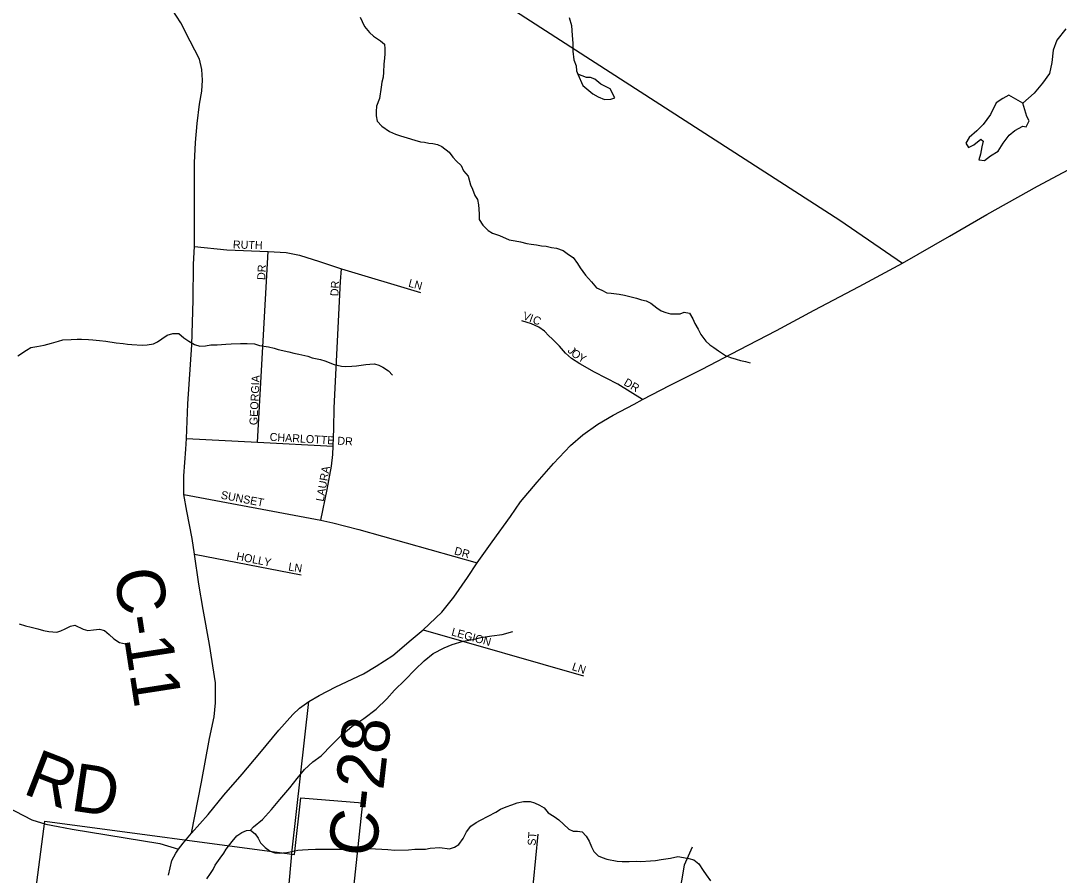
# Model space of a CAD drawing. Extents: x 1310247 to 1664935, y 235267 to 584339.
# Drawn here: x 1518278 to 1524766, y 357083 to 362419 of the extents above; entities that cross this region are included whole.
import ezdxf

# ---------------------------------------------------------------- set-up
doc = ezdxf.new("R2010")
doc.units = 0
for name, color, linetype in [('GM_X_City_Street', 7, 'Continuous'), ('GM_X_Corporation', 7, 'Continuous'), ('GM_X_County_Road', 7, 'Continuous'), ('GM_X_County_Road_Text', 7, 'Continuous'), ('GM_X_Minor_Lake', 7, 'Continuous'), ('GM_X_Minor_River', 7, 'Continuous'), ('GM_X_State_Route', 7, 'Continuous'), ('GM_X_Township_Road', 7, 'Continuous'), ('GM_X_Township_Road_Text', 7, 'Continuous'), ('GM_X_Township_Subdivision', 7, 'Continuous'), ('GM_X_Township_Subdivision_Text', 7, 'Continuous')]:
    doc.layers.add(name, color=color, linetype=linetype)

msp = doc.modelspace()

# ---------------------------------------------------------------- linework, layer by layer
at = {"layer": 'GM_X_City_Street'}
msp.add_lwpolyline([(1519849.1, 356020.4), (1519880.1, 356293.4), (1519914.3, 356582.7), (1519973.8, 357238.6)], dxfattribs=at)
at = {"layer": 'GM_X_Corporation'}
msp.add_lwpolyline([(1518354.2, 356845.4), (1518428.4, 357420.8), (1519987.1, 357211.2), (1520027.7, 357566.1), (1520412.5, 357535.3), (1520260.1, 356104.2)], dxfattribs=at)
at = {"layer": 'GM_X_County_Road'}
for points in [[(1519345.4, 357344.8), (1519406.5, 357663), (1519457, 357935.5), (1519485.5, 358071.7), (1519495.6, 358159.2), (1519493.9, 358283.6), (1519457, 358524.1), (1519418.3, 358742.7), (1519391.4, 358900.8), (1519364.4, 359087.5), (1519349.3, 359185), (1519315.1, 359356.1), (1519297.6, 359460.2), (1519297.1, 359577.2), (1519308.4, 359744.2), (1519313, 359810.1), (1519321.2, 360027.4), (1519346, 360395.8), (1519354.2, 360674.5), (1519357, 360899), (1519362.5, 361009.1), (1519364.3, 361531.5), (1519368.9, 361658.9), (1519380.8, 361777.1), (1519394.6, 361899), (1519408.3, 361979.7), (1519412.9, 362047.5), (1519409.2, 362114.4), (1519394.6, 362178.6), (1519336.8, 362292.3), (1519278.1, 362405.9), (1519196.6, 362530.6)], [(1519973.8, 357238.6), (1520077.9, 358167.8)]]:
    msp.add_lwpolyline(points, dxfattribs=at)
at = {"layer": 'GM_X_Minor_Lake'}
for points in [[(1524538.4, 361905.7), (1524451, 361955.4), (1524412.5, 361933.9), (1524371.9, 361906.5), (1524336.6, 361834.8), (1524289.4, 361771.3)], [(1524289.4, 361771.3), (1524250.7, 361731.8), (1524203.8, 361690.4), (1524181.2, 361654.7), (1524198.8, 361628.3), (1524231.1, 361643.8), (1524275.9, 361679.2), (1524289.7, 361666.9), (1524281.1, 361632.9), (1524274.3, 361586.8), (1524263.7, 361550.9), (1524299.7, 361546.2), (1524336.3, 361575.8), (1524385, 361605.1), (1524415.9, 361654.7), (1524452.8, 361704.3), (1524487.4, 361733.9), (1524538, 361761.1), (1524558, 361756.8), (1524576.7, 361794.6), (1524563.1, 361821), (1524538.4, 361905.7)]]:
    msp.add_lwpolyline(points, dxfattribs=at)
at = {"layer": 'GM_X_Minor_River'}
for points in [[(1520398.8, 362443), (1520410.2, 362414.6), (1520425.6, 362384.2), (1520456.8, 362345.5), (1520482.3, 362322.9), (1520525.7, 362293.9), (1520551.3, 362273.3), (1520552.7, 362243.2), (1520552.1, 362213.1), (1520549.5, 362185.1), (1520546.7, 362149), (1520543.7, 362099), (1520541, 362066.9), (1520534.3, 362037), (1520529.7, 362005), (1520518.1, 361933), (1520501.1, 361885.2), (1520498.4, 361853.2), (1520497.8, 361825.1), (1520505.2, 361792.9), (1520534.5, 361760.2), (1520581.8, 361727.1), (1520619.5, 361712.2), (1520651.3, 361701.6), (1520691.1, 361688.7), (1520740.8, 361673.6), (1520774.6, 361662.9), (1520800.6, 361660.3), (1520826.5, 361655.8), (1520852.4, 361653.2), (1520882.3, 361646.6), (1520908.1, 361634), (1520953.4, 361599), (1520976.7, 361568.4), (1521000.2, 361541.8), (1521029.6, 361515.1), (1521043, 361482.8), (1521072.3, 361448.1), (1521087.2, 361395.6), (1521100.6, 361367.2), (1521113.8, 361328.9), (1521131.2, 361302.4), (1521138.5, 361270.2), (1521141.4, 361214), (1521142.6, 361177.8), (1521163.9, 361143.3), (1521197.2, 361110.5), (1521224.8, 361091.9), (1521268.6, 361078.9), (1521330.1, 361051.6), (1521365.9, 361044.8), (1521399.8, 361038.1), (1521439.7, 361029.2), (1521465.6, 361024.7), (1521499.5, 361019.9), (1521531.4, 361013.3), (1521561.3, 361010.6), (1521593.2, 361003.9), (1521625.1, 360999.3), (1521666.9, 360984.3), (1521700.4, 360959.6), (1521728, 360941), (1521755.2, 360904.3), (1521772.6, 360875.8), (1521805.7, 360831), (1521842.8, 360788.1), (1521874.1, 360751.4), (1521907.8, 360736.6), (1521939.4, 360719.9), (1521967.4, 360717.3), (1522017.3, 360712.3), (1522049.2, 360705.6), (1522075.1, 360699)], [(1521703.6, 362439.8), (1521718.5, 362389.3), (1521719.9, 362359.2), (1521723.2, 362327), (1521726.2, 362278.8), (1521727.1, 362228.7), (1521734, 362176.4), (1521747.2, 362138), (1521750.6, 362107.8), (1521757.2, 362085)], [(1524806.9, 362369.1), (1524749.6, 362297.7), (1524728.5, 362235.8), (1524719.2, 362159.7), (1524704, 362089.7), (1524660.9, 362030.1), (1524609.7, 361966.8), (1524538.4, 361905.7)], [(1521757.2, 362085), (1521789.9, 362016.1), (1521851.2, 361962.8), (1521885, 361944.2), (1521924.9, 361927.5), (1521965, 361928.8), (1521989.2, 361938.4), (1521960.1, 361995.1), (1521902.4, 362024.2), (1521864.8, 362055)], [(1521864.8, 362055), (1521836.9, 362065.5), (1521812.8, 362065.9), (1521757.2, 362085)], [(1522075.1, 360699), (1522124.8, 360686), (1522156.7, 360677.3), (1522184.6, 360670.7), (1522214.3, 360656), (1522251.7, 360627.1), (1522279.3, 360608.5), (1522307.1, 360597.9), (1522336.9, 360589.2), (1522366.9, 360588.6), (1522397, 360590), (1522423.2, 360599.5), (1522455.1, 360592.8), (1522476.4, 360558.3), (1522489.7, 360527.9), (1522509, 360493.4), (1522526.4, 360460.9), (1522557.5, 360418.2), (1522583, 360395.6), (1522608.7, 360379), (1522636.3, 360358.4), (1522679.7, 360329.4), (1522711.4, 360316.7), (1522747.2, 360305.9), (1522775.1, 360297.3), (1522804.9, 360290.6), (1522834.8, 360282)], [(1518258.8, 360327.4), (1518313.6, 360362.3), (1518341.9, 360377.8), (1518378.1, 360385.1), (1518424.3, 360394.1), (1518470.6, 360405.2), (1518512.9, 360418.3), (1518541.1, 360425.8), (1518593.2, 360428.7), (1518631.2, 360429.9), (1518657.3, 360431.4), (1518701.2, 360428.5), (1518727.2, 360425.9), (1518769.2, 360423), (1518809.1, 360418.2), (1518874.9, 360408.8), (1518916.9, 360403.9), (1518944.8, 360399.3), (1518972.8, 360396.7), (1519036.7, 360393.4), (1519066.8, 360394.8), (1519107, 360402), (1519133.2, 360413.4), (1519159.6, 360432.9), (1519192.1, 360456.3), (1519228.4, 360465.6), (1519266.4, 360466.8), (1519295.9, 360440.1), (1519327.4, 360417.4), (1519363, 360396.6), (1519396.8, 360387.9), (1519432.9, 360389.1), (1519465, 360394.5), (1519505.1, 360395.6), (1519559.2, 360398.5), (1519593.3, 360401.8), (1519651.4, 360404.6), (1519691.4, 360403.8), (1519737.3, 360400.8), (1519769.2, 360392.1), (1519825, 360383), (1519860.8, 360374.2), (1519886.7, 360365.6), (1519952.4, 360352.2), (1519984.3, 360343.5), (1520014.2, 360336.9), (1520071.9, 360323.6), (1520097.7, 360315.1), (1520149.5, 360304), (1520177.4, 360295.4), (1520236.9, 360272.1), (1520280.8, 360263.1), (1520306.7, 360260.6), (1520346.8, 360261.8), (1520374.8, 360263.2), (1520405, 360268.5), (1520433.1, 360272), (1520459.1, 360275.5), (1520487.2, 360276.9), (1520515, 360268.3), (1520540.8, 360255.7), (1520576.3, 360232.9), (1520599.8, 360206.3)], [(1518267.5, 358652.4), (1518307.3, 358639.5), (1518343.2, 358632.7), (1518384.9, 358621.8), (1518420.7, 358611.1), (1518452.6, 358604.4), (1518502.6, 358601.3), (1518528.8, 358608.8), (1518555.1, 358622.3), (1518589.4, 358637.6), (1518615.6, 358645.1), (1518667.1, 358620), (1518696.9, 358611.3), (1518733, 358614.6), (1518769.1, 358619.8), (1518801, 358611.2), (1518830.5, 358586.5), (1518859.9, 358559.8), (1518895.5, 358537), (1518931.3, 358528.2)], [(1519713.3, 357364.6), (1519732.6, 357383.8), (1519787.5, 357431), (1519844.7, 357492.3), (1519895.9, 357555.8), (1519959.4, 357629), (1520004.4, 357686.5), (1520051.5, 357741.9), (1520102.5, 357791.2), (1520155.3, 357828.5), (1520220.6, 357897.7), (1520279.8, 357955), (1520346.9, 358012), (1520422, 358061), (1520499.2, 358120), (1520564.5, 358185.1), (1520613.5, 358238.5), (1520676.7, 358301.7), (1520742, 358366.9), (1520799.1, 358422.2), (1520854, 358467.4), (1520922.8, 358502.4), (1520973.3, 358523.7), (1521041.9, 358544.6), (1521102.3, 358555.6), (1521152.6, 358566.8), (1521221, 358577.8), (1521285.3, 358586.7), (1521351.8, 358605.7)], [(1521061.9, 357352.6), (1521088.7, 357388.1), (1521123.2, 357411.5), (1521149.5, 357427), (1521246.6, 357477.1), (1521275, 357494.5), (1521309.4, 357509.9), (1521345.7, 357523.2), (1521379.9, 357534.5), (1521418.2, 357543.7), (1521460.1, 357542.8), (1521488, 357534.2), (1521517.7, 357519.6), (1521547.4, 357502.9), (1521572.7, 357472.3), (1521610.3, 357449.4), (1521639.9, 357428.8), (1521669.3, 357402.1), (1521702.6, 357369.3), (1521728.4, 357358.7), (1521756.4, 357358.1), (1521784.4, 357353.6), (1521809.8, 357327), (1521829.1, 357294.5), (1521844.4, 357260), (1521857.8, 357231.7), (1521885.3, 357203), (1521911, 357192.5), (1521938.8, 357181.9), (1522004.6, 357170.5), (1522034.6, 357167.8), (1522078.7, 357168.9), (1522124.7, 357170), (1522152.7, 357167.4), (1522212.8, 357172.1), (1522242.9, 357175.5), (1522279, 357180.8), (1522337.3, 357189.6), (1522383.5, 357198.7), (1522417.4, 357193.9), (1522451.3, 357187.2), (1522483.1, 357178.5), (1522514.6, 357153.8), (1522541.8, 357113.1), (1522559.2, 357084.7), (1522586.4, 357048)], [(1519440.7, 357059.5), (1519463.4, 357093.1), (1519480, 357118.8), (1519492.5, 357144.6), (1519523.4, 357188.1), (1519546.1, 357219.7), (1519560.7, 357245.5), (1519599.7, 357292.8), (1519628.5, 357328.3), (1519658.9, 357349.7), (1519687.2, 357361.2), (1519713.3, 357364.6), (1519742.8, 357342), (1519760.2, 357313.5), (1519775.6, 357285.1), (1519805.1, 357256.4), (1519836.6, 357233.7), (1519864.4, 357223.1), (1519892.4, 357220.5), (1519940.5, 357223.5), (1519970.6, 357230.9), (1520008.8, 357238.1), (1520038.9, 357241.5), (1520072.9, 357242.8), (1520119, 357245.9), (1520189.1, 357244.4), (1520215.1, 357245.9), (1520267.1, 357244.8), (1520293.2, 357246.3), (1520339.2, 357245.3), (1520391.3, 357248.2), (1520417.3, 357247.7), (1520447.3, 357249.1), (1520493.3, 357248.1), (1520533.3, 357245.3), (1520571.3, 357242.5), (1520615.2, 357239.5), (1520699.3, 357241.8), (1520739.4, 357245), (1520765.4, 357244.4), (1520807.5, 357245.6), (1520835.6, 357251), (1520895.7, 357255.8), (1520955.6, 357246.5), (1520987.8, 357257.8), (1521014.2, 357275.3), (1521041, 357310.9), (1521061.9, 357352.6)]]:
    msp.add_lwpolyline(points, dxfattribs=at)
at = {"layer": 'GM_X_State_Route'}
for points in [[(1523786.3, 360906.5), (1524080.5, 361074), (1524313, 361209.5), (1524629.3, 361386.9), (1524951, 361556.6)], [(1519345.4, 357344.8), (1519448.4, 357462.1), (1519546.2, 357582.1), (1519661.7, 357714.5), (1519771.4, 357845.8), (1519890.4, 357988.6), (1519977, 358085.5), (1520019.2, 358125.5), (1520077.9, 358167.8), (1520143.1, 358205.1), (1520246.1, 358260), (1520419.3, 358340.7), (1520499, 358388.1), (1520601.5, 358455), (1520716.7, 358553.3), (1520791.9, 358615.9), (1520908.2, 358726.2), (1520982.8, 358818.5), (1521069.2, 358943.1), (1521130.2, 359033.7), (1521223.4, 359165.1), (1521337.8, 359323.5), (1521400.3, 359415.4), (1521503.1, 359537.9), (1521606.8, 359653.7), (1521712.6, 359766), (1521789.7, 359833.3), (1521882.3, 359899.4), (1521979.2, 359955.6), (1522109.2, 360023.9), (1522162.1, 360053.6), (1522335.1, 360144), (1522535.7, 360244.3), (1522766, 360364.4), (1522999.9, 360484.7), (1523234.3, 360611.2), (1523516.3, 360758.9), (1523786.3, 360906.5)], [(1519201, 357082.2), (1519222.6, 357173.7), (1519247.6, 357219.5), (1519264.2, 357245.3), (1519291.7, 357282.7), (1519345.4, 357344.8)]]:
    msp.add_lwpolyline(points, dxfattribs=at)
at = {"layer": 'GM_X_Township_Road'}
for points in [[(1519290.1, 363801), (1519342.2, 363787.7), (1523394.3, 361174.7), (1523786.3, 360906.5)], [(1514747.5, 359474.8), (1514760.8, 359503.3), (1514783.5, 359536.9), (1514825.6, 359540.2), (1514948.2, 359457.6), (1515278.2, 359216.5), (1515405, 359141.9), (1518027.9, 357593.2), (1518347.3, 357428.6), (1518434.9, 357401.4), (1518511.3, 357385.9), (1518598.9, 357369.8), (1519146.6, 357280.5), (1519264.2, 357245.3)], [(1522418.2, 357107.5), (1522424.9, 357146.7), (1522474.8, 357260.2)], [(1522307.6, 356461.9), (1522308.5, 356468.8), (1522418.2, 357107.5)]]:
    msp.add_lwpolyline(points, dxfattribs=at)
at = {"layer": 'GM_X_Township_Subdivision'}
for points in [[(1519362.5, 361009.1), (1519564.7, 360987.9), (1519823, 360977.6), (1519935.4, 360971.6), (1520018.6, 360955.3), (1520144.8, 360915), (1520282.2, 360870.8), (1520775.4, 360722.8)], [(1519756.7, 359788), (1519823, 360977.6)], [(1520153.4, 359300.1), (1520192.8, 359492.3), (1520219.4, 359638.2), (1520226.8, 359709.9), (1520230.3, 359761.8), (1520233.5, 359872.5), (1520235.7, 360001.2), (1520276.1, 360791.4), (1520282.2, 360870.8)], [(1522162.1, 360053.6), (1522009, 360150.6), (1521861.3, 360225.6), (1521769.9, 360277.3), (1521718.1, 360310.4), (1521681.7, 360342.4), (1521644.2, 360386.4), (1521596.9, 360433.8), (1521577, 360452.5), (1521549.5, 360481.2), (1521514.2, 360505.4), (1521468, 360526.3), (1521407.4, 360546.2)], [(1519313, 359810.1), (1519756.7, 359788), (1520230.3, 359761.8)], [(1519297.6, 359460.2), (1520153.4, 359300.1), (1520228, 359283), (1520391, 359242.7), (1521130.2, 359033.7)], [(1519364.4, 359087.5), (1520028.8, 358959.7)], [(1520791.9, 358615.9), (1521793, 358328.4)], [(1521365.1, 355998.3), (1521416.9, 356403.6), (1521451.7, 356740.4), (1521509.3, 357339.4)]]:
    msp.add_lwpolyline(points, dxfattribs=at)

# ---------------------------------------------------------------- texts
at = {"layer": 'GM_X_County_Road_Text'}
for s, rotation, p in [('C-11', 278.79779, (1518858.7, 358980.6)), ('C-28', 83.47012, (1520494.4, 357188.6))]:
    msp.add_text(s, height=300, rotation=rotation, dxfattribs=at).set_placement(p)
at = {"layer": 'GM_X_Township_Road_Text'}
for s, rotation, p in [('R', 338.81902, (1518282.9, 357595.6)), ('D', 351.62471, (1518582.1, 357488.2))]:
    msp.add_text(s, height=300, rotation=rotation, dxfattribs=at).set_placement(p)
at = {"layer": 'GM_X_Township_Subdivision_Text'}
for s, rotation, p in [('RUTH', 358.49332, (1519602.8, 360997.3)), ('DR', 86.98872, (1519804.4, 360799.2)), ('DR', 86.98872, (1520261.9, 360698)), ('LN', 345.25955, (1520696.1, 360759.4)), ('V', 340.24473, (1521409.7, 360556.8)), ('I', 339.13193, (1521450.8, 360542)), ('C', 336.83649, (1521470.9, 360534.3)), ('J', 312.35603, (1521690.9, 360356)), ('O', 321.20097, (1521711.8, 360334)), ('Y', 331.09355, (1521754, 360301.2)), ('GEORGIA', 87.23131, (1519756, 359892.7)), ('DR', 329.54176, (1522040.5, 360146.8)), ('CHARLOTTE DR', 356.73025, (1519831.9, 359796.1)), ('LAURA', 79.59535, (1520169.6, 359414)), ('SUNSET', 349.11463, (1519525.1, 359435.2)), ('HOLLY', 348.9292, (1519621.9, 359052.3)), ('DR', 344.47652, (1520982.3, 359087.4)), ('LN', 351.03269, (1519947.2, 358986.4)), ('LEGION', 344.35759, (1520964.7, 358581.4)), ('LN', 341.56141, (1521717.5, 358365.6)), ('ST', 86.42578, (1521494, 357266.1))]:
    msp.add_text(s, height=50, rotation=rotation, dxfattribs=at).set_placement(p)

doc.saveas('drawing.dxf')
